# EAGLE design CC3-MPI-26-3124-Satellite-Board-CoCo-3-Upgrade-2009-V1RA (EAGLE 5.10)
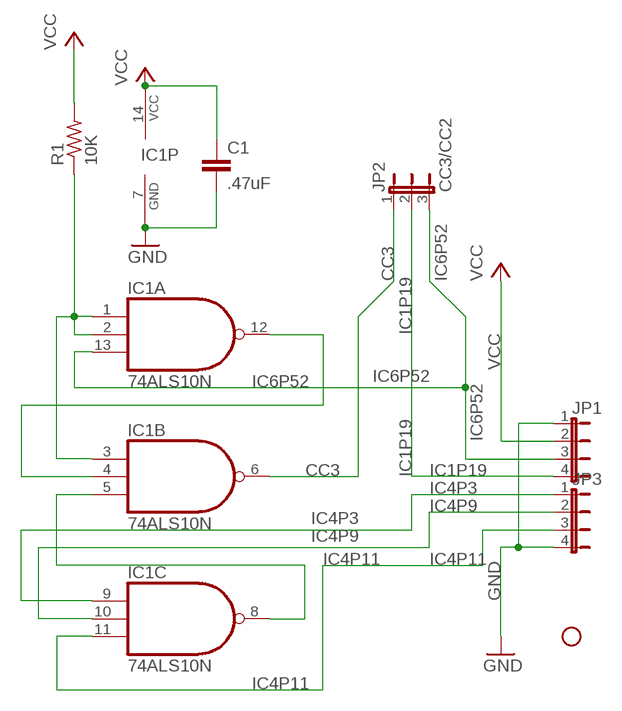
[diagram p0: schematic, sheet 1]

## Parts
C1  .47uF  C2.5/4  [C2.5-4]
IC1  74ALS10N  [DIL14-3]
JP1  JP4E  [JP4]
JP2  CC3/CC2  JP2E  [JP2]
JP3  JP4E  [JP4]
R1  10K  R-US_0207/7  [0207/7]
U$1  SPARKFUN_STAND-OFF  [SPARKFUN_STAND-OFF]

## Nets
CC3: IC1.6(B:O) JP2.1
GND [power]: C1.2 IC1.7(P:GND) JP1.1 JP3.4
IC1P19: JP1.4 JP2.2
IC4P3: IC1.9(C:I0) JP3.1
IC4P9: IC1.10(C:I1) JP3.2
IC4P11: IC1.11(C:I2) JP3.3
IC6P52: IC1.13(A:I2) JP1.3 JP2.3
N$6: IC1.1(A:I0) IC1.2(A:I1) IC1.3(B:I0) R1.1
N$8: IC1.4(B:I1) IC1.12(A:O)
N$9: IC1.5(B:I2) IC1.8(C:O)
VCC [power]: C1.1 IC1.14(P:VCC) JP1.2 R1.2

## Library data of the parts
C1 = capacitor-wima:C: CAPACITOR
IC1 = RetroZilla.org-74xx-us:74*10: Triple 3-input NAND gate
JP1 JP3 = jumper:JP4E: JUMPER
JP2 = jumper:JP2E: JUMPER
R1 = rcl-2:R-US_: RESISTOR, American symbol
U$1 = FDC:SPARKFUN_STAND-OFF: Stand Off

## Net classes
0 default: width 0.203 mm, clearance 0.152 mm
1 power: width 0.762 mm, clearance 0.203 mm

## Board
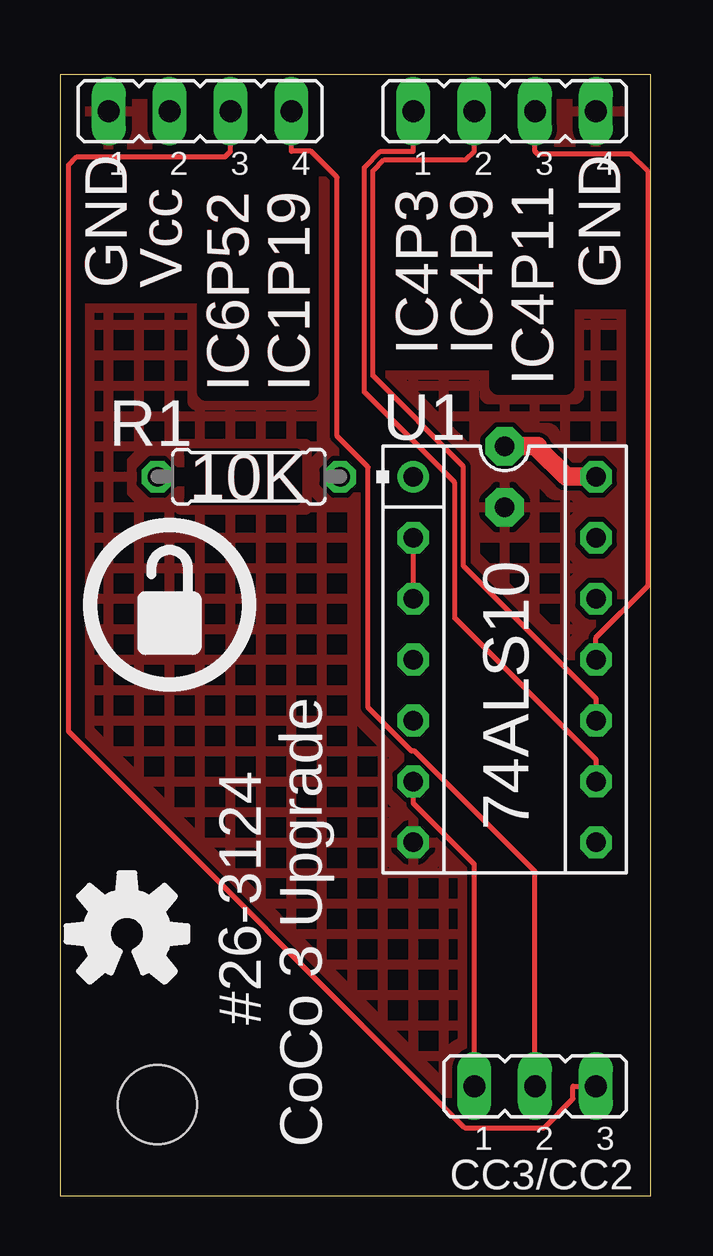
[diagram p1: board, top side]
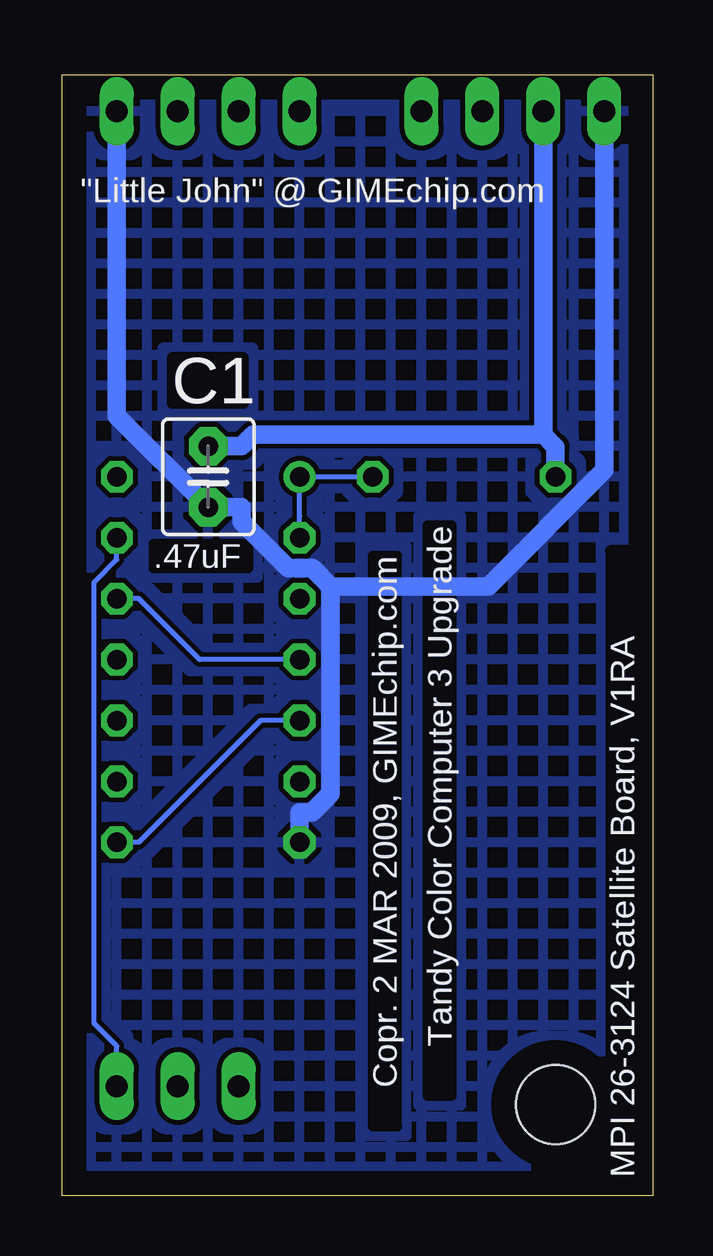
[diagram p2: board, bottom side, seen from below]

Size 24.64 x 46.74 mm. Coordinates in mm from the lower left corner, seen from the top.
Outline: 0,46.74 0,0 24.64,0 24.64,46.74 0,46.74
Copper layers (1*16): Top 0.035mm / dielectric 1.5mm / Bottom 0.035mm
Design rules "default": minimum track width 10mil, minimum drill 24mil, track to track 8mil, track to pad 8mil, pad to pad 8mil, via to via 8mil, smd to smd 8mil, copper to edge 40mil, drill to drill 8mil, minimum pad ring 10mil, minimum via ring 8mil, stop-mask expansion 4mil, vias tented up to drill 0mil, thermal gap 10mil
tRestrict: area 1,33.5 to 10.4,42.7; area 13.7,33.8 to 23.9,42.4

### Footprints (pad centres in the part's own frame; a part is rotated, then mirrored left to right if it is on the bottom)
C2.5-4 = drill 0.813 pad 1.6 octagon: 1 -1.27,0; 2 1.27,0
DIL14-3 = drill 0.813 round: 1 -7.62,-3.81 | drill 0.813 octagon: 2 -5.08,-3.81; 3 -2.54,-3.81; 4 0,-3.81; 5 2.54,-3.81; 6 5.08,-3.81; 7 7.62,-3.81; 8 7.62,3.81; 9 5.08,3.81; 10 2.54,3.81; 11 0,3.81; 12 -2.54,3.81; 13 -5.08,3.81; 14 -7.62,3.81
JP4 = drill 0.914 long: 1 -3.81,0; 2 -1.27,0; 3 1.27,0; 4 3.81,0
JP2 = drill 0.914 long: 1 -2.54,0; 2 0,0; 3 2.54,0
0207/7 = drill 0.813 octagon: 1 -3.81,0; 2 3.81,0
SPARKFUN_STAND-OFF = hole 3.302: 0,0

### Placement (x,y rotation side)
C1  18.54,29.97 270 bottom
IC1  18.54,22.35 270 top
JP1  5.84,45.21 0 top
JP2  19.81,4.57 0 top
JP3  18.54,45.21 0 top
R1  7.87,29.97 180 top
U$1  4.06,3.81 0 top
U$2  [OSHWLOGO_0.3]  4.57,24.64 0 top
U$3  [OSHWLOGO_TOL_0.2]  2.79,10.92 0 top

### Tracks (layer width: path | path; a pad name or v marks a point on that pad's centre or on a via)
CC3
  Top 0.203: IC1.6 14.73,16.36 17.27,13.82 JP2.1
GND
  Bottom 0.762: 13.44,25.4 13.44,16.76 14.22,15.98 14.73,15.98 IC1.7 | 13.44,25.4 14.19,26.16 15.22,26.16 17.16,28.1 17.16,28.7 C1.2 22.35,32.51 JP3.4 | JP1.1 2.03,30.24 6.87,25.4 13.44,25.4
  pour Top (hatched): -0.51,47.75 24.89,47.75 24.89,-0.51 -0.51,-0.51
  pour Bottom (hatched): -0.51,47.75 24.89,47.75 24.89,-0.51 -0.51,-0.51
IC1P19
  Top 0.203: JP1.4 9.65,43.54 10.48,43.54 11.56,42.45 11.56,31.67 12.85,30.37 12.85,20.36 14.66,18.54 14.79,18.54 19.81,13.52 JP2.2
IC4P3
  Top 0.203: IC1.9 22.35,18.19 16.46,24.07 16.46,29.73 12.69,33.5 12.69,42.86 13.37,43.54 14.73,43.54 JP3.1
IC4P9
  Top 0.203: IC1.10 22.35,20.73 16.82,26.26 16.82,30.41 13.05,34.18 13.05,42.71 13.52,43.18 16.92,43.18 17.27,43.54 JP3.2
IC4P11
  Top 0.203: IC1.11 22.35,23.27 24.52,25.44 24.52,42.68 23.78,43.42 19.93,43.42 19.81,43.54 JP3.3
IC6P52
  Top 0.203: JP2.3 21.39,4.57 21.39,4.04 20.19,2.85 16.87,2.85 0.36,19.36 0.36,42.96 0.71,43.31 6.88,43.31 7.11,43.54 JP1.3
  Bottom 0.203: IC1.13 22.35,26.52 23.3,25.57 23.3,7.2 22.35,6.25 JP2.3
N$6
  Top 0.203: IC1.3 IC1.2
  Bottom 0.203: IC1.2 14.73,28.35 IC1.1 R1.1
N$8
  Bottom 0.203: IC1.12 21.44,24.89 18.9,22.35 IC1.4
N$9
  Bottom 0.203: IC1.8 21.44,14.73 16.36,19.81 IC1.5
VCC
  Top 0.762: C1.1 19.93,31.24 19.93,31.15 21.11,29.97 IC1.14
  Bottom 0.762: C1.1 17.16,31.24 16.68,31.72 4.57,31.72 | 4.57,31.72 JP1.2 | 4.57,31.72 4.06,31.22 R1.2

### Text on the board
Top: GND | Vcc | GND | IC4P3 | IC4P9 | IC6P52 | IC1P19 | IC4P11 | 10K
Bottom: C1 | Tandy Color Computer 3 Upgrade | Copr. 2 MAR 2009, GIMEchip.com | .47uF | MPI 26-3124 Satellite Board, V1RA
tPlace: GND | Vcc | GND | IC4P3 | IC4P9 | IC6P52 | IC1P19 | IC4P11 | R1 | U1 | 10K | 74ALS10
bPlace: "Little John" @ GIMEchip.com | C1 | Tandy Color Computer 3 Upgrade | Copr. 2 MAR 2009, GIMEchip.com | .47uF | MPI 26-3124 Satellite Board, V1RA
_tsilk: #26-3124 | CoCo 3 Upgrade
